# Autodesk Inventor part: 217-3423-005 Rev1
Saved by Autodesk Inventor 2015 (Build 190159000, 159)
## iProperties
Created: 2014-11
Part Number: 217-3423-005 Rev1
Material: Generic
Document SubType Name: Modeling
Designer: User
Density: 1 g/cm^3
Appearance: Default
Author: User
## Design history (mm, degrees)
node "217-3423-005 Rev1.ipt1"
node "#9 (0.196) Diameter Hole1"
node "Base1"
